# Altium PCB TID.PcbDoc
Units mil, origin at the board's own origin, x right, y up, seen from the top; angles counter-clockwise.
Board outline 2210.03 x 2160.03 mil, 2 copper layers (Top Layer, Bottom Layer), stack 62 mil thick; 31 components, 12 nets, 59 pads, 64 vias.
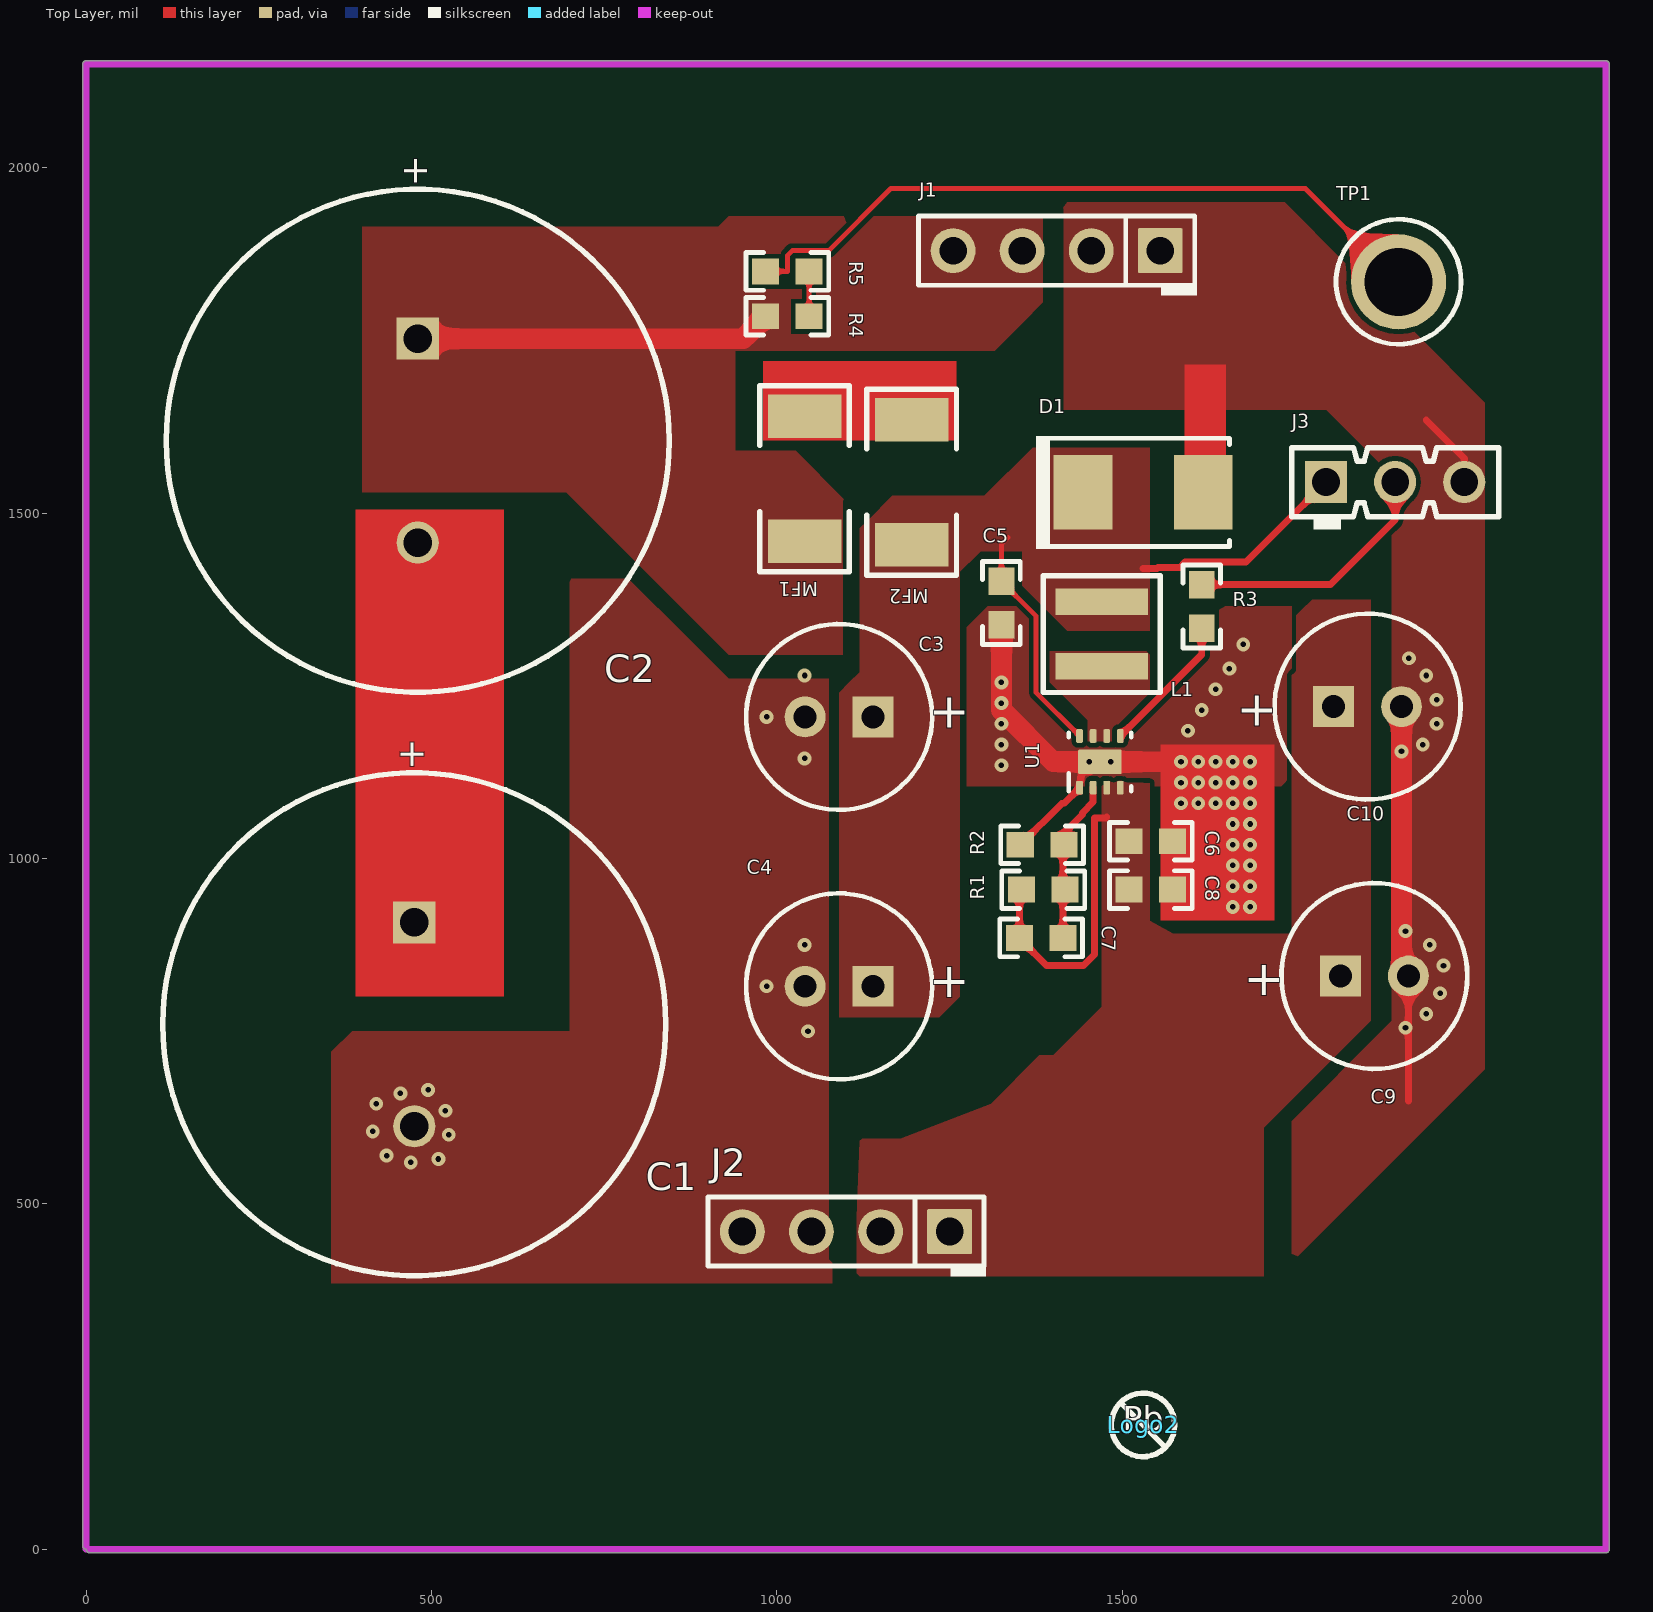
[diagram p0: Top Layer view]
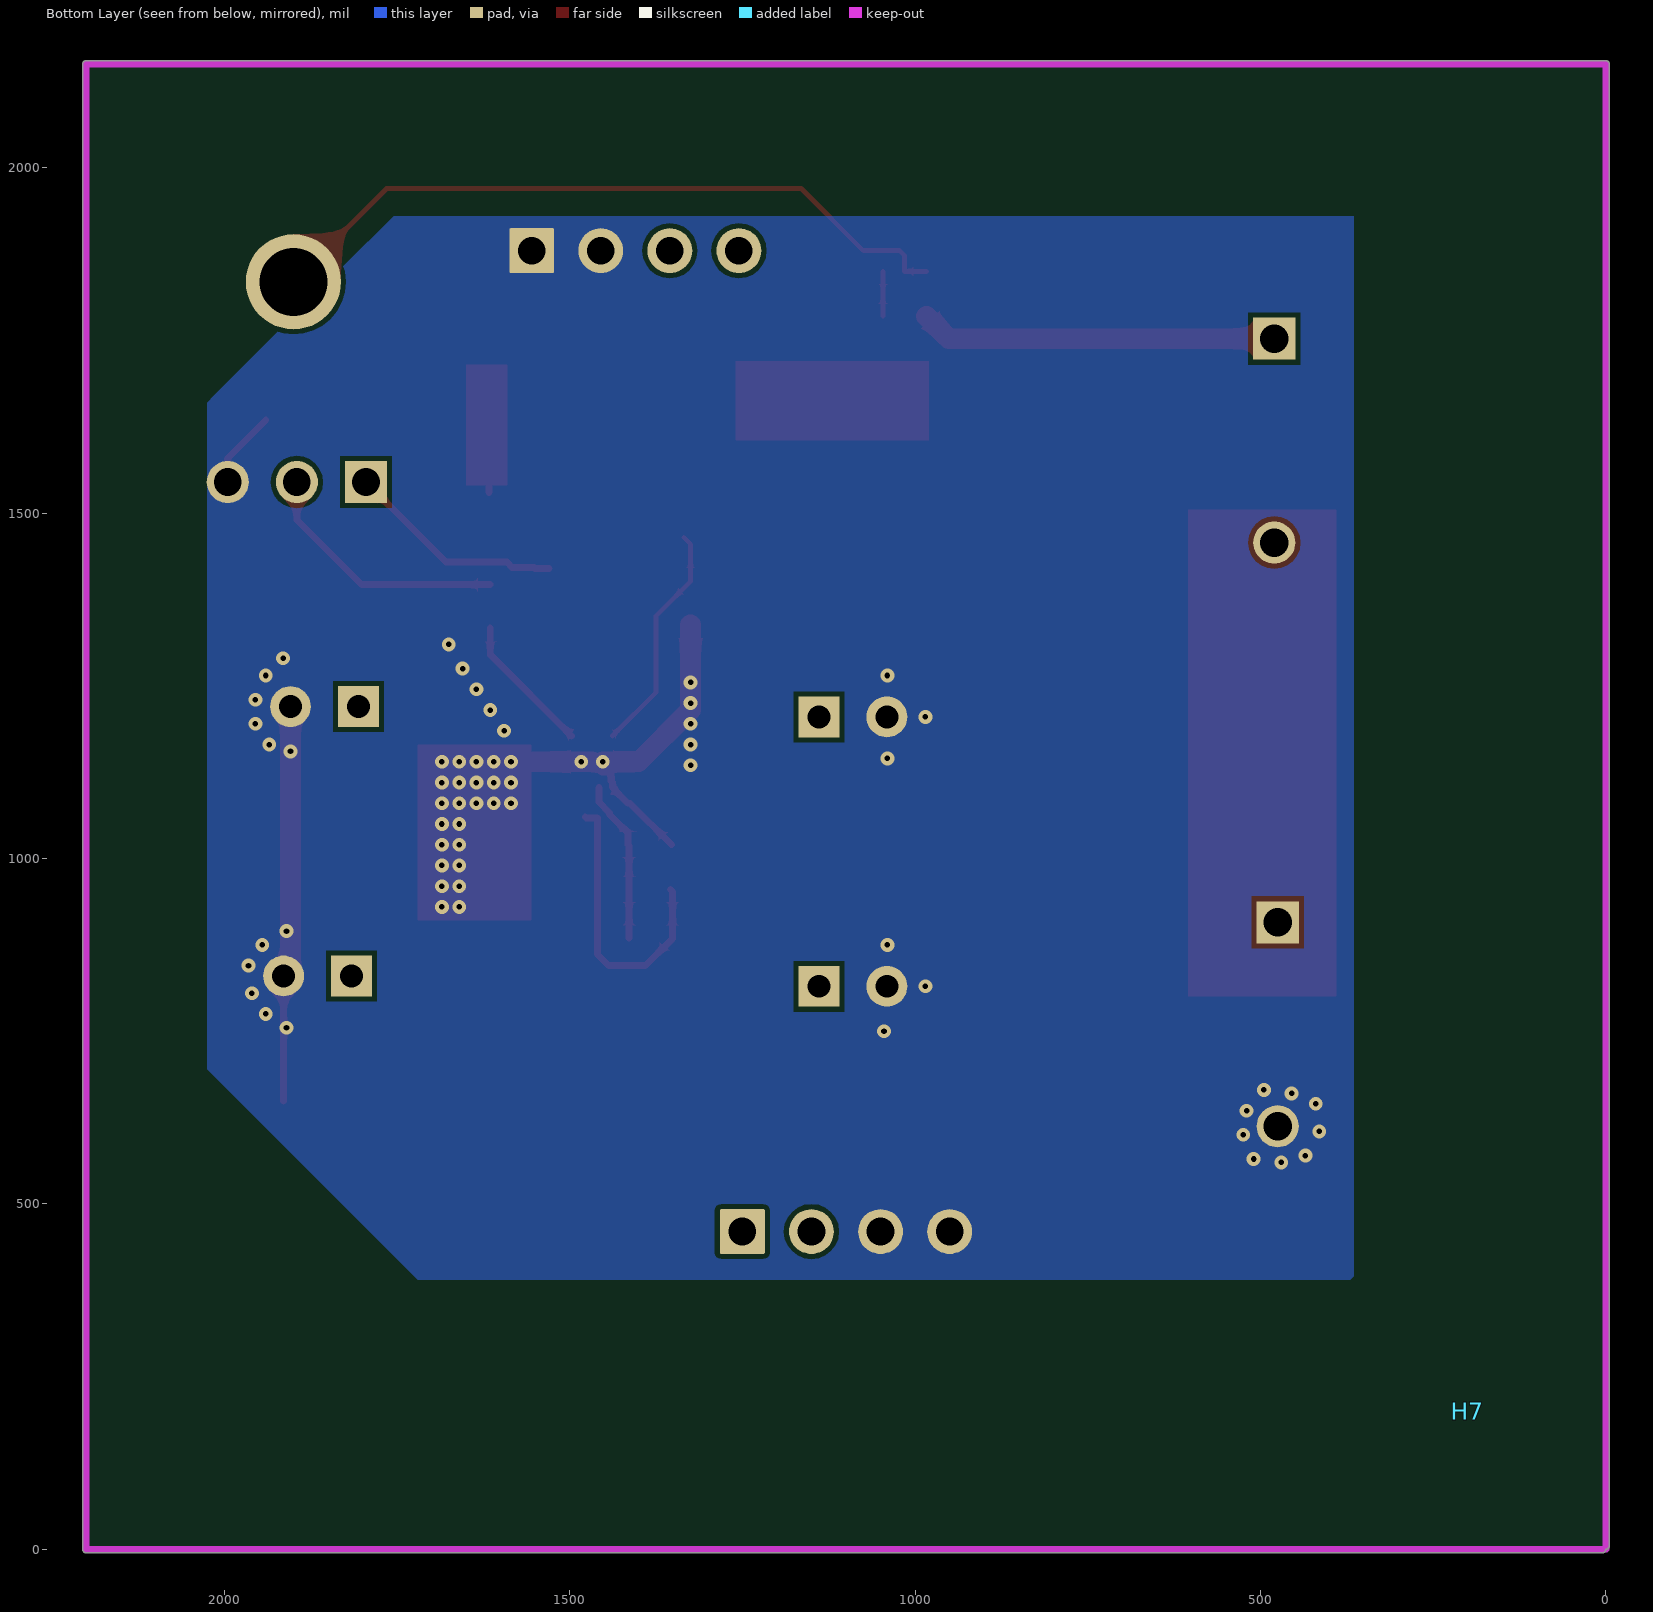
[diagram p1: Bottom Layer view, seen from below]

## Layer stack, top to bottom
Top Solder: solder mask 0.4, Solder Resist, Dk 3.5
Top Layer: signal copper 1.4
Dielectric1: core 59.2, FR-4, Dk 4.8
Bottom Layer: signal copper 1.4
Bottom Solder: solder mask 0.4, Solder Resist, Dk 3.5

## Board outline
-0.01,-0.02 cw(c0,5) -5.01,5 -5.01,2150 cw(c0,2150) 0,2155.01 2200,2155.01 cw(c2200,2150) 2205.01,2150 2205.01,0 cw(c2200,0) 2200,-5.02 5,-5.02 cw(c5,0)

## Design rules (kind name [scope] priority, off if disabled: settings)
AcuteAngle [All] p1: minimum=4.50000000000000E+0001 checktracksonly=FALSE
AssemblyTestPointUsage [All] p1: valid=2
Clearance Clearance_Keepouts [((IsTrack Or IsArc) And Not InPoly) And IsFree and IsKeepOut vs ((IsTrack Or IsArc) And Not InPoly) And IsFree and IsKeepOut] p1: gap=0
Clearance Clearance_BoardEdge_MountingHoles [OnCopper and InComponentClass('Mounting Holes') vs IsKeepOut] p2: gap=40
Clearance Clearance_BoardEdge_Poly [OnCopper and InPoly vs IsKeepOut] p3: gap=25
Clearance Clearance_BoardEdge [OnCopper and Not InComponentClass('Logo') and not InComponentClass('FiducialMark') and not InRegion(1000,500,4000,800) and Not IsKeepout vs IsKeepOut] p4: gap=75
Clearance Clearance_Poly [InPolygon] p5: gap=7
Clearance [All] p6: gap=7.87
ComponentClearance ComponentClearance_MountingHoles_FiducialMarks [InComponentClass('Mounting Holes') vs InComponentClass('FiducialMark')] p1: gap=50 collisioncheckmode=3 verticalgap=10 showdistances=FALSE
ComponentClearance ComponentClearance_Shunt [InComponentClass('Header') vs InComponentClass('Shunt')] p2: gap=0 collisioncheckmode=3 verticalgap=0 showdistances=FALSE
ComponentClearance ComponentClearance_Logo [InComponentClass('Logo')] p3: gap=50 collisioncheckmode=3 verticalgap=10 showdistances=FALSE
ComponentClearance ComponentClearance_ScrewToNut [(HasFootprint('NY PMS 440 0025 PH')) vs (HasFootprint('Keystone_1902C'))] p4: gap=5 collisioncheckmode=3 verticalgap=10 showdistances=FALSE
ComponentClearance ComponentClearance_MountingHoles [InComponentClass('Mounting Holes')] p5: gap=250 collisioncheckmode=3 verticalgap=100000 showdistances=FALSE
ComponentClearance ComponentClearance_SmallPassives [HasFootprint('0201*') or HasFootprint('0402*') or HasFootprint('0508') or HasFootprint('0603*') or HasFootprint('0612') or HasFootprint('0805*') or HasFootprint('0815*') or HasFootprint('0830*') or HasFootprint('1206*') or HasFootprint('1210*') or HasFootprint('1808*') or HasFootprint('1812*') or HasFootprint('1825*') or HasFootprint('2010*') or HasFootprint('2220*') or HasFootprint('2225*') or HasFootprint('2512*') or HasFootprint('2728*') or HasFootprint('3518*') vs HasFootprint('0201*') or HasFootprint('0402*') or HasFootprint('0508') or HasFootprint('0603*') or HasFootprint('0612') or HasFootprint('0805*') or HasFootprint('0815*') or HasFootprint('0830*') or HasFootprint('1206*') or HasFootprint('1210*') or HasFootprint('1808*') or HasFootprint('1812*') or HasFootprint('1825*') or HasFootprint('2010*') or HasFootprint('2220*') or HasFootprint('2225*') or HasFootprint('2512*') or HasFootprint('2728*') or HasFootprint('3518*')] p6: gap=20 collisioncheckmode=3 verticalgap=10 showdistances=FALSE
ComponentClearance ComponentClearance_THtoSMT [IsThruComponent vs IsSMTComponent] p7: gap=100 collisioncheckmode=3 verticalgap=30 showdistances=FALSE
ComponentClearance ComponentClearance_THtoTH [IsThruComponent vs IsThruComponent] p8: gap=118.11 collisioncheckmode=3 verticalgap=30 showdistances=FALSE
ComponentClearance [All] p9: gap=40 collisioncheckmode=3 verticalgap=10 showdistances=FALSE
DiffPairsRouting [All] p1: maxlimit=100 minlimit=10 mostfreqgap=10 toplayer_minwidth=15 toplayer_maxwidth=15 toplayer_prefwidth=15 bottomlayer_minwidth=15 bottomlayer_maxwidth=15 bottomlayer_prefwidth=15 maxuncoupledlength=1000
FabricationTestPointUsage TestPointUsage [All] p1: valid=2 allowmultiple=FALSE
FabricationTestpoint Testpoint [All] p1: side=3 testpointundercomponent=TRUE minsize=40 maxsize=100 preferedsize=60 minholesize=0 maxholesize=40 preferedholesize=32 testpointgrid=1 allowsidetop=TRUE allowsidebottom=TRUE usegrid=TRUE gridtolerance=0.01
FanoutControl Fanout_LCC [IsLCC] p1: bgadir=Out bgaviamode=Centered fanoutstyle=Auto fanoutdirection=Alternating viagrid=1 // Fanout_LCC (Default Rule)
FanoutControl Fanout_BGA [IsBGA] p2: bgadir=Out bgaviamode=Centered fanoutstyle=Auto fanoutdirection=Alternating viagrid=1 // Fanout_BGA (Default Rule)
FanoutControl Fanout_Default [All] p4: bgadir=Out bgaviamode=Centered fanoutstyle=Auto fanoutdirection=Alternating viagrid=1 // Fanout_Default (Default Rule)
FanoutControl Fanout_Small [(CompPinCount < 5)] p5: bgadir=Out bgaviamode=Centered fanoutstyle=Auto fanoutdirection=OutThenIn viagrid=1 // Fanout_Small (Default Rule)
Height [All] p1: minheight=0 maxheight=10000 prefheight=500
HoleSize [All] p1: absolutevalues=TRUE maxlimit=251 minlimit=7 maxpercent=80.000 minpercent=20.000
MinimumAnnularRing MinimumAnnularRing_ThermalPadVias [IsVia and InAnyComponent] p1: minimumring=5.91
MinimumAnnularRing [All] p2: minimumring=5
MinimumSolderMaskSliver MinimumSolderMaskSliver_Logo [InComponentClass('Logo') vs InComponentClass('Logo')] p1: minsoldermaskwidth=0.7
MinimumSolderMaskSliver [All] p2: minsoldermaskwidth=0.94
PlaneConnect [All] p1: planeconnectstyle=Relief reliefexpansion=10 reliefentries=4 reliefconductorwidth=10 reliefairgap=10
PolygonConnect [All] p1: connectstyle=Direct reliefconductorwidth=10 reliefentries=4 polygonreliefangle="90 Angle" airgapwidth=10
RoutingVias ThermalPadVias [IsVia and InAnyComponent] p1: holewidth=7.87 width=19.68 viastyle="Through Hole" minholewidth=7.87 minwidth=19.68 maxholewidth=12.99 maxwidth=23.62
RoutingVias [All] p2: holewidth=16 width=34 viastyle="Through Hole" minholewidth=7.87 minwidth=16 maxholewidth=40 maxwidth=65
SilkToBoardRegionClearance [Not ((IsComment or IsDesignator) And (Hide <> 'False')) and not InRegion(1000,500,4000,800)] p1:
SilkToSilkClearance SilkToSilkClearance_Pb-FreeLogo [(HasFootprint('Pb-Free_Overlay_Medium') OR HasFootprint('Pb-Free_Overlay_Small')) vs (HasFootprint('Pb-Free_Overlay_Medium') OR HasFootprint('Pb-Free_Overlay_Small'))] p1: silktosilkclearance=0
SilkToSilkClearance [All] p2: silktosilkclearance=4
SilkToSolderMaskClearance SilkToComonentPadClearance [IsPad and InAnycomponent] p1: minsilkscreentomaskgap=5 clearancetoexposedcopper=TRUE
SilkToSolderMaskClearance "Silk to Solder Mask Opening" [All] p2: minsilkscreentomaskgap=4 clearancetoexposedcopper=FALSE
SolderMaskExpansion [All] p1: expansion=1.97
UnpouredPolygon [All] p1: allowunpoured=FALSE
Width [All] p1: maxlimit=100 minlimit=6 preferedwidth=10 checkconnectedcopper=TRUE
13 further rules are at their usual default settings.

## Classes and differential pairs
component class Header: J1 J2 J3
component class BlankSheet: C1 C2 C3 C4 C5 C6 C7 C8 C9 C10 D1 J1 J2 J3 L1 MF1 MF2 R1 R2 R3 R4 R5 TP1 U1 U2
component class TID_Hardware: H5 H6 H7 Logo2 ZZ2 ZZ3 ZZ4
component class AssemblyNote: ZZ2 ZZ3 ZZ4

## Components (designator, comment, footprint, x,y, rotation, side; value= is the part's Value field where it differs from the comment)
C1 "EEU-FC1H222" FC_1800x3550 475,760 r270 top
C2 "EEU-FC1H222" FC_1800x3550 480,1605 r270 top
C3 "6SEPC470MW" SEPC_C9 1090,1205 r180 top
C4 "6SEPC470MW" SEPC_C9 1090,815 r180 top
C5 "GRM188R60J106ME84" 0603 1325,1370 r270 top
C6 "GRM188R71C104KA01D" 0603 1541.3,1025 r0 top
C7 "C0603C102K5RACTU" 0603 1382.6,885 r0 top
C8 "C1608X5R0J226M080AC" 0603 1541.3,955 r0 top
C9 "6SEPC470MW" SEPC_C9 1865,830 r0 top
C10 "6SEPC470MW" SEPC_C9 1855,1220 r0 top
D1 "1SMB5918BT3G" SMB 1530,1530 r0 top
H5 "1902C" Keystone_1902C 200,3250 r180 bottom locked
H6 "1902C" Keystone_1902C 4750,3250 r180 bottom locked
H7 "1902C" Keystone_1902C 200,200 r180 bottom locked
J1 "TSW-104-07-G-S" TSW-104-07-G-S 1405,1880 r180 top
J2 "TSW-104-07-G-S" TSW-104-07-G-S 1100,460 r180 top
J3 "TSW-103-07-T-S" Samtec_TSW-103-07-T-S 1895,1545 r0 top
L1 "XFL4015-471MEC" XFL4015 1470,1325 r270 top
Logo2 "Pb-Free Symbol" Pb-Free_Overlay_Small 1530,180 r0 top
MF1 "WSL2010R0100FEA18" 2010 1040,1550 r90 top
MF2 "WSL2010R0100FEA18" 2010 1195,1545 r270 top
R1 "RC0603FR-07402KL" 0603 1385.55,955 r180 top
R2 "CPF0603B100KE" 0603 1383.9,1020 r0 top
R3 "CRCW06031K00FKEA" 0603 1615,1365 r270 top
R4 "RT0603BRD0758R3L" 0603 1015,1785 r0 top
R5 "RT0603BRD0758R3L" 0603 1015,1850 r180 top
TP1 "Suggest using a net name here" Keystone1502-2 1900,1835 r0 top
U1 "TPS61021ADSGR" DSG0008A 1467.64,1140 r90 top
ZZ2 "These assemblies are ESD sensitive, ESD precautions shall be observed." AssemblyNote 185,3829.11 r0 top
ZZ3 "These assemblies must be clean and free from flux and all contaminants. Use of no clean flux is not acceptable." AssemblyNote 185,3740.56 r0 top
ZZ4 "These assemblies must comply with workmanship standards IPC-A-610 Class 2, unless otherwise specified." AssemblyNote 185,3652 r0 top

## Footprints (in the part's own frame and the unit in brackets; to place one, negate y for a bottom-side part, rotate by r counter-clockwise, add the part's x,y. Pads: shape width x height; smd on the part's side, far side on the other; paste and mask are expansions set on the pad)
0603 [mm] "0603 from SM-752 data"
  rect 1x0.95 smd: 1(-0.8,0) 2(0.8,0)
  silkscreen extent -1.52,-0.69 1.52,0.69, body extent -0.87,-0.47 0.87,0.47, height 1
2010 [mm] "Chip Capacitor, Body 5.08x2.54mm, IPC Medium Density"
  rect 1.6x2.7 smd: 1(-2.3,0) 2(2.3,0)
  silkscreen extent -3.42,-1.65 3.42,1.65, body extent -2.73,-1.45 2.73,1.45, height 1.66
AssemblyNote [mil] "Assembly Note"
DSG0008A [mm] "SON, 8-Leads, Body 2x2mm, Pitch 0.5mm, Thermal Pad 1.6x0.9mm, TI Recommended"
  rrect40% 0.5x0.25 smd: 1(-0.95,0.75) 2(-0.95,0.25) 3(-0.95,-0.25) 4(-0.95,-0.75) 5(0.95,-0.75) 6(0.95,-0.25) 7(0.95,0.25) 8(0.95,0.75)
  rrect11% 0.9x1.6 smd paste-0.45: 9(0,0)
  silkscreen extent -1.07,-1.15 1.07,1.15, body extent -1.05,-1.05 1.05,1.05, height 0.8
FC_1800x3550 [mm] "TH, 2-Leads, Dia 18mm, Lead Spacing 7.5mm"
  rect 1.55x1.55 hole 1.05: 1(-3.75,0)
  round 1.55 hole 1.05: 2(3.75,0)
  silkscreen extent -9.25,-9.25 9.25,9.25, body extent -9.18,-9.23 9.22,9.24, height 37.01
Keystone1502-2 [mm] "Double Turret"
  round 3.5 hole 2.5: 1(0,0)
  silkscreen extent -2.3,-2.3 2.3,2.3, body extent -1.6,-1.6 1.59,1.6, height 5.62
Keystone_1902C [mil] "Hex Standoff, 4-40 threaded, nylon"
  body extent -145,-126 146,126, height 501
Pb-Free_Overlay_Small [mil]
  silkscreen extent -46,-46 46,46
Samtec_TSW-103-07-T-S [mm] "Header, 2.54 mm, 3x1, TH"
  rect 1.55x1.55 hole 1.02: 1(-2.54,0)
  round 1.55 hole 1.02: 2(0,0) 3(2.54,0)
  silkscreen extent -3.81,-1.75 3.81,1.27, body extent -3.81,-1.27 3.81,1.27, height 8.39
SEPC_C9 [mm] "PANASONIC"
  rect 1.5x1.5 hole 0.838: 1(-1.25,0)
  round 1.5 hole 0.838: 2(1.25,0)
  silkscreen extent -3.42,-3.42 3.42,3.42, body extent -3.41,-3.41 3.41,3.41, height 9.05
SMB [mil] "Molded Diode, 2-Leads, Body 5.4x3.6mm, IPC Medium Density, based on OnSemi component dimensions"
  rect 85x107.99 smd: 1(-87.01,0) 2(87.01,0)
  silkscreen extent -155,-82 125,82, body extent -106,-71 106,71, height 91
TSW-104-07-G-S [mm] "Samtec 100mil, 1x4, 230 mil above insulator"
  rrect6% 1.65x1.65 hole 1.016: 1(-3.81,0)
  round 1.65 hole 1.016: 2(-1.27,0) 3(1.27,0) 4(3.81,0)
  silkscreen extent -5.16,-1.27 5.08,1.65, body extent -5.08,-1.27 5.08,1.27, height 8.38
XFL4015 [mm] "SMD, 2-Leads, Body 4x4mm"
  rect 0.98x3.4 smd: 1(-1.185,0) 2(1.185,0)
  silkscreen extent -2.15,-2.15 2.15,2.15, body extent -2.15,-2.15 2.15,2.15, height 1.6

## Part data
C1 C2: "CAP, AL, 2200 μF, 50 V, +/- 20%, 0.023 ohm, AEC-Q200 Grade 2, TH"
C3 C4 C9 C10: "CAP, AL, 470 μF, 6.3 V, +/- 20%, 0.007 ohm, TH"
C5: "CAP, CERM, 10 μF, 6.3 V, +/- 20%, X5R, 0603"
C6: "CAP, CERM, 0.1 μF, 16 V, +/- 10%, X7R, 0603"
C7: "CAP, CERM, 1000 pF, 50 V, +/- 10%, X7R, 0603"
C8: "CAP, CERM, 22 μF, 6.3 V, +/- 20%, X5R, 0603"
D1: "Diode, Zener, 5.1 V, 550 mW, SMB"
H5 H6 H7: "Standoff, Hex, 0.5\"L #4-40 Nylon"
J1 J2: "Header, 100mil, 4x1, Gold, TH"
J3: "Header, 2.54 mm, 3x1, Tin, TH"
L1: "Inductor, Shielded, Composite, 470 nH, 3.5 A, 0.0076 ohm, SMD"
Logo2: library part Pb-Free
MF1 MF2: "RES, 0.01, 1%, 1 W, 2010"
R1: "RES, 402 k, 1%, 0.1 W, 0603"
R2: "RES, 100 k, 0.1%, 0.063 W, 0603"
R3: "RES, 1.00 k, 1%, 0.1 W, 0603"
R4 R5: "RES, 58.3, 0.1%, 0.1 W, 0603"
TP1: library part 1502-2, "Terminal, Turret, TH, Double"
U1: library part TPS61021DSGR, "3-A BOOST CONVERTER WITH 0.5V ULTRA-LOW INPUT VOLTAGE, DSG0008A"
ZZ2 ZZ3 ZZ4: library part AssemblyNote

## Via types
v1: diameter 20, hole 8, Top Layer to Bottom Layer, 62 vias
v2: diameter 19.68, hole 7.87, Top Layer to Bottom Layer, 2 vias

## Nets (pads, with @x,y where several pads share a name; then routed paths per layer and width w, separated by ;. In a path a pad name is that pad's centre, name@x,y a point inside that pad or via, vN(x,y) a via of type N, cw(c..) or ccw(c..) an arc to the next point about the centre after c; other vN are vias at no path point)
FB: C7.2 R1.1 R2.2 U1.2 | length 235.7
  Top Layer w10: C7.2 1414.09,1018.7 R2.2 1415.39,1037.03 1442.13,1063.76 1442.13,1066.16 1457.8,1081.83 U1.2
GND: C1.2 C3.2 C4.2 C5.2 C6.2 C8.2 C9.2 C10.2 D1.2 J1.1 J1.2 J2.3 J2.4 J3.3 R2.1 U1.1 U1.9 | length 1329.3
  Top Layer w10: R2.1 1412.4,1080 1415.51,1080 U1.1 1438.11,1110.47 1440,1112.36 1440,1125.31 1452.95,1125.31 U1.9 ; D1.2 1617.01,1595.59 ; 1914.21,649.21 C9.2 ; 1940,1635 1995,1580 J3.3
  Top Layer w30: C5.2 1325,1215 1400,1140 v2(1451.89,1140) ; U1.9 v1(1585,1140) ; C10.2 1904.21,840 C9.2
  other v1: 470,560 510,565 435,570 525,600 415,605 520,635 420,645 455,660 495,665 1045,750 1910,755 1940,775 1960,805 985,815 1965,845 1040,875 1945,875 1910,895 1660,930 1685,930 1660,960 1685,960 1660,990 1685,990 1660,1020 1685,1020 1660,1050 1685,1050 1585,1080 1610,1080 1635,1080 1660,1080 1685,1080 1585,1110 1610,1110 1635,1110 1660,1110 1685,1110 1325,1135 1610,1140 1635,1140 1660,1140 1685,1140 1040,1145 1904.21,1155 1325,1165 1935,1165 1595,1185 1325,1195 1955,1195 985,1205 1615,1215 1325,1225 1955,1230 1635,1245 1325,1255 1040,1265 1940,1265 1655,1275 1915,1290 1675,1310
  other v2: 1483.39,1140
GPRS_POWER_EN: J3.2 R3.1 | length 373.7
  Top Layer w10: R3.1 1801.5,1396.5 1895,1490 J3.2
NetC1_1: C1.1 C2.2
NetMF1_2: MF1.2 MF2.1
NetR3_2: R3.2 U1.5 | length 204.9
  Top Layer w10: U1.5 1615,1295.24 R3.2
NetR4_2: R4.2 R5.1 | length 65
  Top Layer w7: R4.2 R5.1
SENSE_VBAT_EXT: R5.2 TP1.1 | length 1035.8
  Top Layer w7: R5.2 1015.44,1850 1015.44,1873.41 1022.1,1880.07 1075.07,1880.07 1165,1970 1765,1970 TP1.1
SW: L1.2 U1.6 U1.7
VIN: C2.1 J1.3 J1.4 MF1.1 R4.1 | length 516.9
  Top Layer w30: C2.1 880,1752.64 951.14,1752.64 R4.1
VO: C6.1 C7.1 C8.1 C9.1 C10.1 J2.1 J2.2 R1.2 U1.3 U1.4 | length 419.9
  Top Layer w10: R1.2 1351.1,952.05 C7.1 1351.1,883.9 1390,845 1444.09,845 1460,860.91 1460,1058.76 1476.01,1058.76 1477.48,1060.23
VPOWER: C3.1 C4.1 C5.1 D1.1 J3.1 L1.1 MF2.2 U1.8 | length 680.4
  Top Layer w7: 1335,1465 1325,1455 C5.1 1375,1351.5 1375,1240.51 U1.8
  Top Layer w10: 1530,1420 1550,1420 1551.51,1421.51 1583.43,1421.51 1590.97,1429.06 1679.06,1429.06 J3.1 J3.1@1795,1520

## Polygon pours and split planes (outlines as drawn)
VPOWER on Top Layer "Top Layer-No Net 3" (solid, remove dead copper, pour order 18): 1540,1595 1540,1330 1420,1330 1360,1390 1355,1395 1355,1445 1295,1445 1290,1440 1265,1415 1265,1340 1265,800 1235,770 1090,770 1090,1240 1105,1255 1120,1270 1120,1405 1120,1477.99 1132.01,1490 1167.01,1525 1257.99,1525 1300,1525 1370,1595 1540,1595
VIN on Top Layer "Top Layer-No Net 5" (solid, remove dead copper, pour order 17): 1385,1930 1385,1805 1355,1775 1315,1735 925,1735 925,1905 915,1915 930,1930 1375,1930
VIN on Top Layer "Top Layer-No Net 2" (solid, remove dead copper, pour order 16): 400,1915 400,1530 695,1530 930,1295 1095,1295 1095,1517.91 1097.09,1520 1027.09,1590 940,1590 940,1920 930,1930 915,1915 400,1915
GND on Top Layer "Top Layer-No Net 8" (solid, remove dead copper, pour order 15): 635,1465 700,1400 700,750 385,750 355,720 355,710 355,385 1080,385 1080,415 1075,420 1075,1260 930,1260 870,1320 785,1405 695,1405
GND on Top Layer "Top Layer-No Net 7" (solid, remove dead copper, pour order 14): 1415,1940 1415,1650 1795,1650 1820,1625 1890,1555 1890,1375 1890,765 1880,755 1745,620 1745,415 2025,695 2025,1660 1735,1950 1725,1950 1411.97,1950
VO on Top Layer "Top Layer-No Net 6" (solid, remove dead copper, pour order 12): 1515,830 1400,715 1380,715 1310,645 1178.44,594.17 1123.82,594.36 1120,595 1115.51,479.91 1115.51,399.49 1120,395 1130,395 1705,395 1705,715 1715,725 1645,795 1480,795
SW on Top Layer "Top Layer-No Net" (solid, remove dead copper, pour order 11): 1450,1170 1485,1170 1485,1185 1540,1240 1540,1245 1540,1295 1535,1300 1395,1300 1395,1255 1450,1200 1450,1170
GND on Top Layer "Top Layer-No Net 4" (solid, remove dead copper, pour order 19): 1275,1320 1275,1105 1730,1105 1735,1110 1745,1120 1745,1365 1305,1365 1294.64,1354.64 1275,1335 1275,1325
VO on Top Layer "Top Layer-No Net 1" (solid, remove dead copper, pour order 13): 1467.64,1119.11 1470,1116.75 1470,835 1470,615.83 1590,495.83 1595.83,490 1700,490 1700,605 1860,765 1860,775 1860,1375 1775,1375 1760,1360 1745.38,1345.38 1745.38,890.95 1574.05,890.95 1540,910 1540,925 1540,1117.14 1476.11,1117.14 1473.78,1119.47
GND on Bottom Layer "Bottom Layer-No Net" (solid, remove dead copper, pour order 20): 365,395 370,390 1720,390 2025,695 2025,1660 2015,1670 1755,1930 1705,1930 365,1930 365,390

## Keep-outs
Keep-Out Layer:
  lines w10: 0,0 2200,0 2200,2050 2200,2150 0,2150 0,0
  text ".Layer_Name" at 577,-858.49 h60

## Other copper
Top Layer:
  rectangle net NetMF1_2: 980,1605 1260,1720
  rectangle net GND: 1590,1540 1650,1715
  rectangle net NetC1_1: 390,800 605,1505
  rectangle net GND: 1555,910 1720,1165
  text ".Layer_Name" at 577,-858.49 h60
Bottom Layer:
  text ".Layer_Name" at 577,-858.49 h60

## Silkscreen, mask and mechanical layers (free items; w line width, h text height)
Top Overlay:
  text ".Layer_Name" at 577,-858.49 h60
Bottom Overlay:
  text ".Layer_Name" at 577,-858.49 h60
Top Paste:
  text ".Layer_Name" at 577,-858.49 h60
Bottom Paste:
  text ".Layer_Name" at 577,-858.49 h60
Top Solder:
  text ".Layer_Name" at 577,-858.49 h60
  text ".Layer_Name" at 577,-858.49 h60
Bottom Solder:
  text ".Layer_Name" at 577,-858.49 h60
Drill Guide:
  text ".Layer_Name" at 577,-858.49 h60
M1 Board Outline:
  lines w10: 0,5 0,2150 2195,2150 2195,0 5,0
  text ".Layer_Name" at 577,-858.49 h60
M2 Board Dimensions:
  rectangle: 0,-275 125,-150
  rectangle: 125,-400 500,-275
  lines w7: 0,-275 1000,-275 ; 125,-400 125,-150 ; 250,-400 250,-150 ; 500,-400 500,-150 ; 750,-400 750,-150 ; 0,-400 1000,-400 1000,-150 0,-150 0,-400
  text ".Layer_Name" at 577,-858.49 h60
M3 3D STEP Top:
  text ".Layer_Name" at 577,-858.49 h60
M4 3D STEP Bottom:
  text ".Layer_Name" at 577,-858.49 h60
M5 Assembly Top:
  lines w10: -292,-930.17 6308,-930.17 ; -292,-726.83 6310,-726.83 ; -292,-523.5 -292,-1133.5 3713,-1133.5 6310,-1133.5 6310,-523.5 -291.5,-523.5 -291.5,-1133.5 1284,-1133.5 ; 2173,-1133.5 2173,-523.5 ; 3440,-726.83 3440,-523.5 ; 4280,-726.83 4280,-523.5 ; 4902,-1140 4902,-937.17
  text "COMPONENTS MARKED 'DNP' SHOULD NOT BE POPULATED." at 1153.5,-318.5 h60
  text "ASSEMBLY VARIANT:" at 1153,-434 h60
  text ".VariantName" at 2189,-434 h60
  text "PCB VIEWED FROM TOP SIDE" at -228.5,-655.67 h60
  text "BOARD #:" at 2248,-655.67 h60
  text ".PRJ_Number" at 2793.5,-655.67 h60
  text "REV:" at 3638,-655.67 h60
  text ".PCB_Rev" at 3929.5,-655.67 h60
  text "SVN REV:" at 4476,-655.67 h60
  text ".VersionControl_RevNumber" at 4982,-655.67 h60
  text "TID #:" at 2248,-859 h60
  text ".TID" at 2793.5,-859 h60
  text "PLOT NAME =" at -228.5,-1064.34 h60
  text ".plot_File_Name" at 577,-1064.34 h60
  text "GENERATED    :" at 2250,-1064.34 h60
  text ".Print_Date" at 3119.5,-1064.34 h60
  text ".Print_Time" at 3848.5,-1064.34 h60
  text "TEXAS INSTRUMENTS" at 5113,-1064.34 h60
M6 Assembly Bottom:
  lines w10: -292.5,-727.33 6309.5,-727.33 ; -290.5,-930.67 6309.5,-930.67 ; 1115.5,-1140.5 1115.5,-937.67 ; 1737.5,-727.33 1737.5,-524 ; 2577.5,-727.33 2577.5,-524 ; 3844.5,-1134 3844.5,-524 ; 4733.5,-1134 6309,-1134 6309,-524 -292.5,-524 -292.5,-1134 2304.5,-1134 6309.5,-1134 6309.5,-524
  text "COMPONENTS MARKED 'DNP' SHOULD NOT BE POPULATED." at 6102,-318 h60
  text ".VariantName" at 5058,-434 h60
  text "ASSEMBLY VARIANT:" at 6097,-434 h60
  text ".VersionControl_RevNumber" at 1035.5,-656.17 h60
  text "SVN REV:" at 1541.5,-656.17 h60
  text ".PCB_Rev" at 2088,-656.17 h60
  text "REV:" at 2379.5,-656.17 h60
  text ".PRJ_Number" at 3224,-656.17 h60
  text "BOARD #:" at 3769.5,-656.17 h60
  text "PCB VIEWED FROM BOTTOM SIDE" at 6246,-656.17 h60
  text ".TID" at 3224,-859.5 h60
  text "TID #:" at 3769.5,-859.5 h60
  text "TEXAS INSTRUMENTS" at 904.5,-1064.84 h60
  text ".Print_Time" at 2169,-1064.84 h60
  text ".Print_Date" at 2898,-1064.84 h60
  text "GENERATED    :" at 3767.5,-1064.84 h60
  text ".plot_File_Name" at 5440.5,-1064.84 h60
  text "PLOT NAME =" at 6246,-1064.84 h60
M9 Title Sheet:
  drawing of 57 lines, arcs and shapes, not listed
  text "1" at 739.84,8036.5 h70
  text "2" at 3235.5,8036.5 h70
  text "3" at 5724.84,8036.5 h70
  text "4" at 8231.51,8036.5 h70
  text "5" at 10730.5,8036.5 h70
  text "6" at 13235.5,8036.5 h70
  text "A" at -416.5,6893.5 h70
  text "A" at 14383.5,6893.5 h70
  text "B" at -416.5,4513.5 h70
  text "B" at 14383.5,4513.5 h70
  text "C" at -416.5,2138.5 h70
  text "C" at 14383.5,2138.5 h70
  text "PROJECT TITLE:" at 11343.5,277.5 h45
  text ".PRJ_Title" at 11393.5,144.17 h70
  text "DESIGNED FOR:" at 11343.5,-23.5 h45
  text ".PRJ_Customer" at 11393.5,-163.5 h70
  text "D" at -416.5,-231.5 h70
  text "D" at 14383.5,-231.5 h70
  text "FILE NAME:" at 11343.5,-323.5 h45
  text ".PCB_File_Name_No_Path" at 11393.5,-443.5 h70
  text "Texas Instruments (TI) and/or its licensors do not warrant the accuracy or completeness of this specification" at 6374,-605.34 h45
  text "ENGINEER:" at 11343.5,-613.5 h45
  text "LAYOUT BY:" at 12848.5,-613.5 h45
  text "or any information contained therein. TI and/or its licensors do not warrant that this design will meet" at 6329.01,-718 h45
  text ".PRJ_Engineer" at 11393.5,-768.49 h70
  text ".PCB_Layout" at 12899,-768.49 h70
  text "the specifications, will be suitable for your application or fit for any particular purpose, or will operate in" at 6329.01,-830.67 h45
  text ".Layer_Name" at 577,-858.49 h60
  text "ALTIUM DESIGNER VERSION:" at 12848.5,-923.5 h45
  text "an implementation. TI and/or its licensors do not warrant that the design is production worthy. You should" at 6329.01,-943.33 h45
  text "completely validate and test your design implementation to confirm the system functionality for your application." at 6374,-1056 h45
  text ".print_Scale" at 11393.5,-1056.83 h70
  text ".Application_BuildNumber" at 12899,-1056.83 h70
  text "1" at 739.84,-1263.5 h70
  text "2" at 3235.5,-1263.5 h70
  text "3" at 5724.84,-1263.5 h70
  text "4" at 8231.51,-1263.5 h70
  text "5" at 10730.5,-1263.5 h70
  text "6" at 13235.5,-1263.5 h70
M10 Fab Notes:
  drawing of 173 lines, arcs and shapes, not listed
  text "DESIGN INFORMATION" at 12377.02,6201 h60
  text "MIN. TRACK WIDTH:" at 11732.46,6021 h60
  text "8" at 12828.7,6021 h60
  text "MIL" at 12983.46,6021 h60
  text "MIN. CLEARANCE:" at 11732.46,5889 h60
  text "0.2" at 12768.7,5889 h60
  text "mm" at 12983.46,5889 h60
  text "MIN. VIA PAD SIZE:" at 11732.46,5757 h60
  text "24" at 12798.71,5757 h60
  text "MIL" at 12983.46,5757 h60
  text "0.05mm (2MIL)" at 12427.46,5615.29 h60
  text "MINIMUM ANNULAR RING" at 11403.23,5611 h60
  text "EXTERNAL" at 13135.46,5611 h60
  text "PER" at 11603.23,5493 h60
  text "IPC-D-275 CLASS 2 LEVEL C" at 11823.23,5493 h60
  text "MIL, HOLES" at 13311.46,5380.71 h60
  text "+/-" at 12919,5380 h60
  text "+/-" at 13773,5380 h60
  text "REGISTRATION TOLERANCES:" at 11403.23,5375 h60
  text "METAL" at 12603,5375 h60
  text "5" at 13179.2,5375 h60
  text "3" at 14012.2,5375 h60
  text "MIL" at 14128.46,5375 h60
  text "+/-" at 13773,5262 h60
  text "HOLE SIZE TOLERANCE (UNLESS OTHERWISE SPECIFIED):" at 11403.23,5257 h60
  text "3" at 14012.2,5257 h60
  text "MIL" at 14128.46,5257 h60
  text "MATERIAL:" at 11328.46,5047.54 h60
  text "FR-4 High Tg" at 12314.9,4907.21 h60
  text "FR-408" at 11749.46,4898.64 h60
  text "OTHER" at 13237.46,4898.64 h60
  text "X" at 12160,4895 h60
  text "62 MIL (1.6mm) +/-10%" at 12069.56,4735.92 h60
  text "THICKNESS:" at 11403.23,4731.64 h60
  text "X" at 11941.4,4731.64 h60
  text "OTHER" at 13354.46,4731.64 h60
  text "TOLERANCE:" at 11403.23,4573.64 h60
  text "X" at 12242.53,4573.64 h60
  text "ANSI IPC-6012 TYPE 3 CLASS 2" at 12429.48,4573.64 h60
  text "OTHER +/-" at 12429.46,4417.64 h60
  text "BOW & TWIST:" at 11403.23,4260.64 h60
  text "X" at 12242.53,4260.64 h60
  text "ANSI IPC-6012 TYPE 3 CLASS 2" at 12429.48,4260.64 h60
  text "OTHER +/-" at 12429.46,4102.13 h60
  text "DRILLING:" at 11328.46,3963.64 h60
  text "REFERENCE:" at 11403.23,3846.64 h60
  text "X" at 12051.46,3846.64 h60
  text "AS SHOWN" at 12238.46,3846.64 h60
  text "X" at 12952.46,3846.64 h60
  text "NC_DRILL FILES" at 13089.46,3846.64 h60
  text "PTH COPPER THICKNESS:" at 11403.23,3688.64 h60
  text "X" at 12533.46,3688.64 h60
  text "20-30 um" at 12670.46,3688.64 h60
  text "OTHER" at 13387.46,3688.64 h60
  text "BOARD FINISH:" at 11328.46,3529.64 h60
  text "SILKSCREEN:" at 11483.68,3411.64 h60
  text "X" at 12432.46,3411.64 h60
  text "TOP" at 12558.46,3411.64 h60
  text "X" at 12942.46,3411.64 h60
  text "BOTTOM" at 13069.46,3411.64 h60
  text "SILKSCREEN COLOR:" at 11483.68,3244.64 h60
  text "X" at 12431.42,3244.64 h60
  text "WHITE" at 12558.46,3244.64 h60
  text "OTHER" at 13069.46,3244.64 h60
  text "X" at 12562.42,3085.44 h60
  text "GREEN" at 12689.46,3085.44 h60
  text "OTHER" at 13307.46,3085.44 h60
  text "SOLDER RESIST COLOR:" at 11483.68,3074.64 h60
  text "X" at 12562.42,2915.44 h60
  text "MATTE" at 12689.46,2915.44 h60
  text "SEMI-GLOSS" at 13307,2914.8 h60
  text "X" at 13557.42,2730.44 h60
  text "IMMERSION GOLD (ENIG)" at 12389.46,2726.92 h60
  text "ENEPIG" at 13727,2723.64 h60
  text "SURFACE FINISH:" at 11328.46,2722.64 h60
  text "IMM. TIN/SILVER OR EQUIV" at 11658,2565.64 h60
  text "OTHER" at 13089.46,2565.64 h60
  text "ARRAY/PANEL:" at 11328.46,2386.64 h60
  text "CUT AND TRIM PER M1 BOARD OUTLINE" at 12389.46,2382.35 h60
  text "N.C. ROUTE" at 12389.46,2230.64 h60
  text "X" at 13068.46,2230.64 h60
  text "V. SCORE" at 13255.46,2230.64 h60
  text "CERTIFICATION:" at 11328.46,2093.64 h60
  text "MATERIALS AND WORKMANSHIP FOR ALL PCBS" at 12053.46,2093.64 h60
  text "TO MEET OR EXCEED THE REQUIREMENTS OF:" at 12053.46,1995.64 h60
  text "X" at 11679.96,1859.13 h60
  text "ANSI IPC-A-600F CLASS ->" at 11818.96,1859.13 h60
  text "X" at 13458.02,1859.13 h60
  text "2" at 13576.96,1859.14 h60
  text "1" at 13261.96,1857.64 h60
  text "3" at 13930.96,1857.64 h60
  text "X" at 12494.02,1699.64 h60
  text "RoHS" at 12630.96,1699.64 h60
  text "OTHER" at 13275.36,1699.64 h60
  text "PER ORDER" at 13672.42,1699.64 h60
  text "ALL BOARDS MUST MEET OR EXCEED UL94-V0 REQUIREMENTS." at 11356,1534 h60
  text "PCB MUST BEAR THE UL94V-0 UL REGISTERED MATERIAL ID NUMBER" at 11356,1414 h60
  text "ADDITIONAL REQUIREMENTS:" at 11328.46,1240.64 h60
  text "MICROSECTION:" at 11403.23,1125.64 h60
  text "YES" at 12308.96,1125.64 h60
  text "REQUIRED" at 13170.46,969.49 h60
  text "BARE BOARD ELEC. TEST:" at 11403.23,966.64 h60
  text "NONE" at 12708.96,966.64 h60
  text "X" at 13043.46,966.64 h60
  text "PER ORDER" at 13762.46,966.64 h60
  text ".Layer_Name" at 577,-858.49 h60
M11 Gerber Information:
  lines w10: -292,-930.17 6308,-930.17 ; -292,-726.83 6310,-726.83 ; -292,-523.5 -292,-1133.5 3713,-1133.5 6310,-1133.5 6310,-523.5 -291.5,-523.5 -291.5,-1133.5 1284,-1133.5 ; 2173,-1133.5 2173,-523.5 ; 3440,-726.83 3440,-523.5 ; 4280,-726.83 4280,-523.5 ; 4902,-1140 4902,-937.17
  text "ALL ARTWORK VIEWED FROM TOP SIDE" at -228.5,-655.67 h60
  text "BOARD #:" at 2248,-655.67 h60
  text ".PRJ_Number" at 2793.5,-655.67 h60
  text "REV:" at 3638,-655.67 h60
  text ".PCB_Rev" at 3929.5,-655.67 h60
  text "SVN REV:" at 4476,-655.67 h60
  text ".VersionControl_RevNumber" at 4982,-655.67 h60
  text "LAYER NAME =" at -228.5,-858.49 h60
  text "TID #:" at 2248,-859 h60
  text ".TID" at 2793.5,-859 h60
  text "PLOT NAME =" at -228.5,-1064.34 h60
  text ".plot_File_Name" at 577,-1064.34 h60
  text "GENERATED    :" at 2250,-1064.34 h60
  text ".Print_Date" at 3119.5,-1064.34 h60
  text ".Print_Time" at 3848.5,-1064.34 h60
  text "TEXAS INSTRUMENTS" at 5113,-1064.34 h60
M12 Stackup:
  drawing of 191 lines, arcs and shapes, not listed
  text "Layer" at 9790.34,7830 h60
  text "Name" at 10200.26,7830 h60
  text "Material" at 11130,7830 h60
  text "Thickness" at 11989.77,7830 h60
  text "Constant" at 12639.6,7830 h60
  text "Board Layer Stack" at 13209.46,7830 h60
  text "1" at 9790.34,7710 h60
  text "Top Overlay" at 10200.26,7710 h60
  text "2" at 9790.34,7590 h60
  text "Top Solder" at 10200.26,7590 h60
  text "Solder Resist" at 11130,7590 h60
  text "0.40mil" at 11989.77,7590 h60
  text "3.5" at 12639.6,7590 h60
  text "---------" at 12005,7475 h40
  text "2oz" at 12390,7475 h40
  text "3" at 9790.34,7470 h60
  text "Top Layer" at 10200.26,7470 h60
  text "Copper" at 11130,7470 h60
  text "1.40mil" at 11989.77,7470 h60
  text "4" at 9790.34,7350 h60
  text "Dielectric1" at 10200.26,7350 h60
  text "FR-4" at 11130,7350 h60
  text "59.20mil" at 11989.77,7350 h60
  text "4.8" at 12639.6,7350 h60
  text "---------" at 11995,7245 h40
  text "2oz" at 12390,7235 h40
  text "5" at 9790.34,7230 h60
  text "Bottom Layer" at 10200.26,7230 h60
  text "Copper" at 11130,7230 h60
  text "1.40mil" at 11989.77,7230 h60
  text "6" at 9790.34,7110 h60
  text "Bottom Solder" at 10200.26,7110 h60
  text "Solder Resist" at 11130,7110 h60
  text "0.40mil" at 11989.77,7110 h60
  text "3.5" at 12639.6,7110 h60
  text "7" at 9790.34,6990 h60
  text "Bottom Overlay" at 10200.26,6990 h60
  text ".Layer_Name" at 577,-858.49 h60
M13 Component Bodies Top:
  text ".Layer_Name" at 577,-858.49 h60
M14 Component Bodies Bottom:
  text ".Layer_Name" at 577,-858.49 h60
M15 Courtyards Top:
  text ".Layer_Name" at 577,-858.49 h60
M16 Courtyards Bottom:
  text ".Layer_Name" at 577,-858.49 h60
Drill Drawing:
  circle w1: c5677.9,3258.91 r20.77
  lines w1: 5657.13,2500.79 5667.51,2500.79 5667.51,2490.41 5688.28,2490.41 5688.28,2500.79 5698.67,2500.79 5698.67,2521.56 5688.28,2521.56 5688.28,2531.95 5667.51,2531.95 5667.51,2521.56 5657.13,2521.56 5657.13,2500.79 ; 5657.13,2615.03 5698.67,2615.03 5698.67,2656.57 5657.13,2656.57 5657.13,2615.03 ; 5657.13,2739.65 5677.9,2750.04 5698.67,2739.65 5688.28,2760.42 5698.67,2781.19 5677.9,2770.81 5657.13,2781.19 5667.51,2760.42 5657.13,2739.65 ; 5657.13,2885.05 5677.9,2864.27 5698.67,2885.05 5677.9,2905.82 5657.13,2885.05 ; 5657.13,3030.44 5698.67,3030.44 5677.9,2988.9 5657.13,3030.44 ; 5657.13,3113.52 5657.13,3123.9 5667.51,3134.29 5657.13,3144.68 5657.13,3155.06 5667.51,3155.06 5677.9,3144.68 5688.28,3155.06 5698.67,3155.06 5698.67,3144.68 5688.28,3134.29 5698.67,3123.9 5698.67,3113.52 5688.28,3113.52 5677.9,3123.9 5667.51,3113.52 5657.13,3113.52 ; 5665.44,2623.34 5690.36,2623.34 5690.36,2648.26 5665.44,2648.26 5665.44,2623.34
  lines w12: 5600,2453.02 7629.11,2453.02 ; 5600,3325.38 7629.11,3325.38 ; 5948.13,2328.4 5948.13,3450 ; 6290.32,2328.4 6290.32,3450 ; 6937.06,2328.4 6937.06,3450 ; 7206.38,2328.4 7206.38,3450 ; 5600,2328.4 7629.11,2328.4 7629.11,3450 5600,3450 5600,2328.4
  text "Symbol" at 5674.77,3362.76 h72
  text "Quantity" at 5985.52,3362.76 h72
  text "Finished Hole Size" at 6327.7,3362.76 h72
  text "Plated" at 6974.45,3362.76 h72
  text "Hole Type" at 7243.77,3362.76 h72
  text "2" at 5985.52,3238.14 h60
  text "7.87mil (0.200mm)" at 6327.7,3238.14 h60
  text "PTH" at 6974.45,3238.14 h60
  text "Round" at 7243.77,3238.14 h60
  text "62" at 5985.52,3113.52 h60
  text "8.00mil (0.203mm)" at 6327.7,3113.52 h60
  text "PTH" at 6974.45,3113.52 h60
  text "Round" at 7243.77,3113.52 h60
  text "8" at 5985.52,2988.9 h60
  text "33.00mil (0.838mm)" at 6327.7,2988.9 h60
  text "PTH" at 6974.45,2988.9 h60
  text "Round" at 7243.77,2988.9 h60
  text "8" at 5985.52,2864.27 h60
  text "40.00mil (1.016mm)" at 6327.7,2864.27 h60
  text "PTH" at 6974.45,2864.27 h60
  text "Round" at 7243.77,2864.27 h60
  text "3" at 5985.52,2739.65 h60
  text "40.16mil (1.020mm)" at 6327.7,2739.65 h60
  text "PTH" at 6974.45,2739.65 h60
  text "Round" at 7243.77,2739.65 h60
  text "4" at 5985.52,2615.03 h60
  text "41.34mil (1.050mm)" at 6327.7,2615.03 h60
  text "PTH" at 6974.45,2615.03 h60
  text "Round" at 7243.77,2615.03 h60
  text "1" at 5985.52,2490.41 h60
  text "98.43mil (2.500mm)" at 6327.7,2490.41 h60
  text "PTH" at 6974.45,2490.41 h60
  text "Round" at 7243.77,2490.41 h60
  text "88 Total" at 5985.52,2365.79 h60
  text ".Layer_Name" at 577,-858.49 h60

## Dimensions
0,-400 to 1000,-400 on M2 Board Dimensions
0,0 to 0,2155.01 on M2 Board Dimensions
0,0 to -5.01,5 on M2 Board Dimensions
